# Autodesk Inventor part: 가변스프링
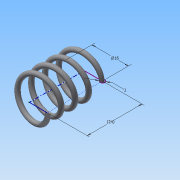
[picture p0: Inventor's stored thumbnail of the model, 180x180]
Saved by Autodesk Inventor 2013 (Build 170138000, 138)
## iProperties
Created: 2015-09
Part Number: 가변스프링
Material: 일반
Document SubType Name: Modeling
Designer: Administrator
Density: 1 g/cm^3
Author: Administrator
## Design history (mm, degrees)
sketch "스케치1"
  geometry: L1 (0, 0)-(8, 0); L2 (8, 0)-(8, 24); L3 (8, 24)-(0, 24); L4 (0, 24)-(0, 0); C1 r 1 at (8, 24); 1 further point
  constraints: 8 end point, 2 coincident, 2 parallel, 1 centre point, 1 horizontal, 1 perpendicular
  dimensions: "d0" = 16 diameter of L2 L4; "d2" = 24 distance between parallel lines of L1 L3 (derived); "d3" = 2 diameter of C1
feature "코일1" pitch "d4" = 10; turns "d6" = 4; dims "d5" = 24 (= d2), "d7" = 0, angle "d8" = 90 deg, angle "d9" = 90 deg, "d10" = 0, "d11" = 0
feature "분할1"
node "작업 평면1"
feature "분할2"
node "솔리드1"
other parameters: "d12" = 90 deg
